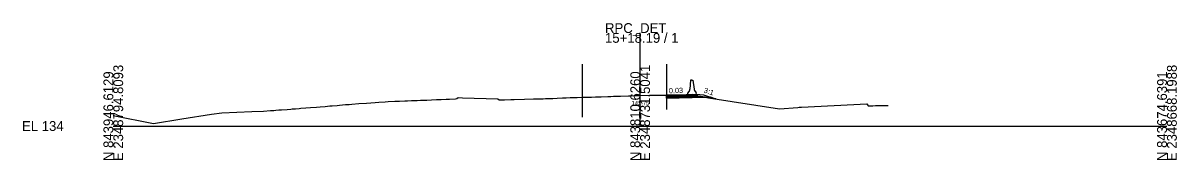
# Model space of a CAD drawing. Extents: x -26 to 2348728, y -10 to 843971.
# Drawn here: x -25.7 to 302.8, y 6490.3 to 6529.4 of the extents above; entities that cross this region are included whole.
import ezdxf

# ---------------------------------------------------------------- set-up
doc = ezdxf.new("R2010")
doc.units = 0
for name, color, linetype in [('Default', 7, 'Continuous'), ('Exist Cross Section Cell', 7, 'Continuous'), ('Exist XS Center Line Elevation Label', 7, 'Continuous'), ('Exist XS Ground Line', 7, 'Continuous'), ('Old_Level_1', 7, 'Continuous'), ('Prop CMT Pvmt Course 1', 7, 'Continuous'), ('Prop CMT Pvmt Course 2', 7, 'Continuous'), ('Prop CMT Pvmt Course 3', 7, 'Continuous'), ('Prop CMT Pvmt Surface Shoulder', 7, 'Continuous'), ('Prop CMT Shld Paved Course 1', 7, 'Continuous'), ('Prop CMT Shld Paved Course 2', 7, 'Continuous'), ('Prop CMT Shld Paved Course 3', 7, 'Continuous'), ('Prop CMT Slope Grass', 7, 'Continuous'), ('Prop CMT Subgrade Earthwork', 7, 'Continuous'), ('Prop XS Earthwork Shape', 7, 'Continuous'), ('Prop XS Side Slope Text', 7, 'Continuous'), ('Scratch_Level_2', 7, 'Continuous'), ('Typical Median Barrier CELL', 7, 'Continuous')]:
    doc.layers.add(name, color=color, linetype=linetype)

# ---------------------------------------------------------------- blocks, each defined once
blk = doc.blocks.new('TYPE T DOUBLE FACE BARRIER')
at = {"layer": 'Typical Median Barrier CELL'}
for p, q in [((-0.33, 3.83), (-0.6, 1.3)), ((0, 3.83), (-0.33, 3.83)), ((0, 3.83), (0.33, 3.83)), ((0.33, 3.83), (0.6, 1.3)), ((-0.75, 0.91), (-1.21, 0.25)), ((-1.21, -0.17), (-1.21, 0.25)), ((0, 0), (0, 0)), ((0.75, 0.91), (1.21, 0.25)), ((1.21, -0.17), (1.21, 0.25)), ((-1.21, -0.17), (1.21, -0.17))]:
    blk.add_line(p, q, dxfattribs=at)
for centre, start, end in [((-1.43, 1.38), 325.0039, 353.9447), ((1.43, 1.38), 186.0553, 214.9937)]:
    blk.add_arc(centre, 0.833, start, end, dxfattribs=at)

msp = doc.modelspace()

# ---------------------------------------------------------------- linework, layer by layer
at = {"layer": 'Exist Cross Section Cell'}
for p, q in [((150, 6500), (150, 6526.56)), ((0, 6500), (150, 6500)), ((150, 6500), (300, 6500))]:
    msp.add_line(p, q, dxfattribs=at)
at = {"layer": 'Exist XS Ground Line'}
msp.add_lwpolyline([(0, 6503.04), (11.41, 6500.68), (19.49, 6502.01), (28, 6503.36), (30.87, 6503.8), (39.43, 6504.13), (42.75, 6504.27), (44.73, 6504.39), (45.16, 6504.42), (45.67, 6504.47), (46.32, 6504.54), (47.09, 6504.58), (47.88, 6504.63), (49.48, 6504.75), (50.57, 6504.84), (50.97, 6504.87), (51.9, 6504.95), (52.95, 6505.03), (53.41, 6505.07), (54.83, 6505.17), (56.18, 6505.27), (57.81, 6505.39), (58.9, 6505.48), (60.36, 6505.61), (61.62, 6505.72), (62.29, 6505.78), (63.69, 6505.9), (64.39, 6505.96), (66.1, 6506.1), (67.19, 6506.18), (67.96, 6506.24), (69.95, 6506.4), (72.13, 6506.57), (74.51, 6506.72), (75.58, 6506.79), (77.41, 6506.91), (78.23, 6506.96), (80.19, 6507.06), (80.64, 6507.08), (81.53, 6507.11), (83.02, 6507.17), (83.74, 6507.2), (84.93, 6507.25), (86.51, 6507.31), (87.44, 6507.35), (89.26, 6507.42), (90.58, 6507.48), (92.03, 6507.53), (93.36, 6507.59), (94.74, 6507.65), (95.74, 6507.7), (97.4, 6507.77), (97.79, 6507.81), (98.22, 6508.12), (99.46, 6508.08), (109.44, 6507.77), (109.85, 6507.51), (110.32, 6507.49), (111.34, 6507.51), (113.18, 6507.54), (114.1, 6507.57), (117.04, 6507.67), (119.6, 6507.73), (120.44, 6507.75), (121.54, 6507.77), (122.4, 6507.8), (123.07, 6507.83), (125.13, 6507.9), (126.34, 6507.95), (127.9, 6508.03), (128.22, 6508.04), (128.95, 6508.07), (130.11, 6508.1), (130.62, 6508.12), (132.08, 6508.16), (133.45, 6508.2), (134.88, 6508.25), (135.76, 6508.27), (136.16, 6508.28), (137.27, 6508.33), (138.92, 6508.38), (140.81, 6508.45), (141.67, 6508.47), (142.42, 6508.5), (144.43, 6508.55), (146.66, 6508.63), (147.15, 6508.65), (148.9, 6508.7), (150, 6508.75), (152.68, 6508.82), (154.55, 6508.83), (155.44, 6508.83), (157.12, 6508.84), (157.5, 6508.84), (158.05, 6508.85), (158.52, 6508.85), (161.34, 6508.82), (164.01, 6508.61), (167.85, 6508.3), (168.47, 6508.25), (169.51, 6508.07), (189.7, 6504.86), (194.93, 6505.32), (195.24, 6505.34), (195.97, 6505.38), (214.54, 6506.3), (214.96, 6505.8), (216.27, 6505.78), (217.03, 6505.87), (219.82, 6505.84), (220.59, 6505.85)], dxfattribs=at)
at = {"layer": 'Prop CMT Pvmt Course 1'}
for p, q in [((157.5, 6508.84), (157.5, 6508.59)), ((162, 6508.97), (162, 6508.72))]:
    msp.add_line(p, q, dxfattribs=at)
at = {"layer": 'Prop CMT Pvmt Course 2'}
for p, q in [((157.5, 6508.59), (157.5, 6508.26)), ((162, 6508.72), (162, 6508.39))]:
    msp.add_line(p, q, dxfattribs=at)
at = {"layer": 'Prop CMT Pvmt Course 3'}
for p, q in [((157.5, 6508.26), (157.5, 6507.92)), ((162, 6508.39), (162, 6508.06))]:
    msp.add_line(p, q, dxfattribs=at)
at = {"layer": 'Prop CMT Pvmt Surface Shoulder'}
msp.add_line((157.5, 6508.84), (166, 6509.09), dxfattribs=at)
at = {"layer": 'Prop CMT Shld Paved Course 1'}
for p, q in [((157.5, 6508.84), (166, 6509.09)), ((166.24, 6508.85), (157.5, 6508.59)), ((157.5, 6508.59), (157.5, 6508.84)), ((162, 6508.72), (162, 6508.97)), ((166, 6509.09), (166.24, 6508.85))]:
    msp.add_line(p, q, dxfattribs=at)
at = {"layer": 'Prop CMT Shld Paved Course 2'}
for p, q in [((157.5, 6508.59), (166.24, 6508.85)), ((157.5, 6508.26), (157.5, 6508.59)), ((166.57, 6508.53), (157.5, 6508.26)), ((162, 6508.39), (162, 6508.72)), ((166.24, 6508.85), (166.57, 6508.53))]:
    msp.add_line(p, q, dxfattribs=at)
at = {"layer": 'Prop CMT Shld Paved Course 3'}
for p, q in [((157.5, 6508.26), (166.57, 6508.53)), ((157.5, 6507.92), (157.5, 6508.26)), ((162, 6508.06), (162, 6508.39)), ((166.57, 6508.53), (167.07, 6508.52)), ((167.07, 6508.52), (167.37, 6508.22)), ((167.37, 6508.22), (157.5, 6507.92))]:
    msp.add_line(p, q, dxfattribs=at)
at = {"layer": 'Prop CMT Slope Grass'}
for p, q in [((135.96, 6508.28), (135.96, 6508.28)), ((157.5, 6508.84), (157.5, 6508.84)), ((162, 6508.97), (162, 6508.97)), ((166, 6509.09), (168, 6508.93)), ((168, 6508.93), (171.6, 6507.73))]:
    msp.add_line(p, q, dxfattribs=at)
at = {"layer": 'Prop CMT Subgrade Earthwork'}
for q in [(157.5, 6508.84), (169.92, 6508.3)]:
    msp.add_line((157.5, 6507.92), q, dxfattribs=at)
at = {"layer": 'Prop XS Earthwork Shape'}
for points in [[(157.5, 6507.92), (168.42, 6508.25), (167.85, 6508.3), (164.01, 6508.61), (161.34, 6508.82), (158.52, 6508.85), (158.05, 6508.85), (157.5, 6508.84)], [(169.92, 6508.3), (171.6, 6507.73), (169.51, 6508.07), (168.47, 6508.25), (168.42, 6508.25)]]:
    msp.add_lwpolyline(points, close=True, dxfattribs=at)
at = {"layer": 'Scratch_Level_2'}
for p, q in [((133.45, 6517.61), (133.45, 6502.52)), ((157.5, 6517.61), (157.5, 6504.68))]:
    msp.add_line(p, q, dxfattribs=at)

# ---------------------------------------------------------------- block references
at = {"layer": 'Old_Level_1', "rotation": 1.7178872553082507}
msp.add_blockref('TYPE T DOUBLE FACE BARRIER', (164.79, 6509.23), dxfattribs=at)

# ---------------------------------------------------------------- texts
at = {"layer": 'Default'}
msp.add_text('0.03', height=1.5, rotation=1.7184, dxfattribs=at).set_placement((158.21, 6509.33))
at = {"layer": 'Exist Cross Section Cell'}
for s, p in [('RPC_DET', (140, 6526.56)), ('15+18.19 / 1', (140, 6523.76)), ('EL 134', (-26, 6498.6))]:
    msp.add_text(s, height=2.8, dxfattribs=at).set_placement(p)
for s, p in [('N 843946.6129', (0, 6490)), ('E 2348794.8093', (2.8, 6490)), ('N 843810.6260', (150, 6490)), ('E 2348731.5041', (152.8, 6490)), ('N 843674.6391', (300, 6490)), ('E 2348668.1988', (302.8, 6490))]:
    msp.add_text(s, height=2.8, rotation=90, dxfattribs=at).set_placement(p)
at = {"layer": 'Exist XS Center Line Elevation Label'}
msp.add_text('142.75', height=1.2, dxfattribs=at).set_placement((147.55, 6505.94))
at = {"layer": 'Prop XS Side Slope Text'}
msp.add_text('3:1', height=1.5, rotation=341.5668, dxfattribs=at).set_placement((167.99, 6509.61))

doc.saveas('drawing.dxf')
